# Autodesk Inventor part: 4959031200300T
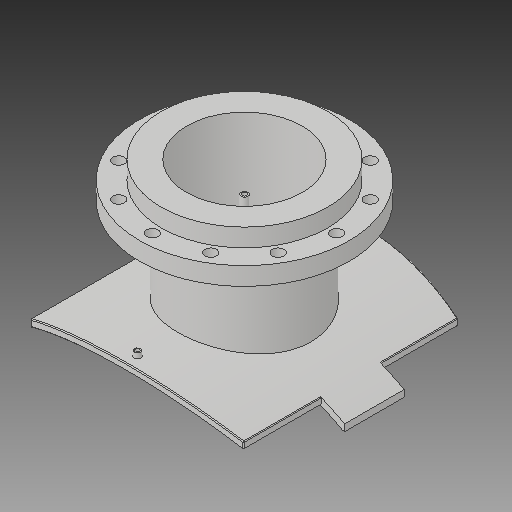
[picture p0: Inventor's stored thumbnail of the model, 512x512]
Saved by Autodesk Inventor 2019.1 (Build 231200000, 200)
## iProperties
Created: 2017-10
Part Number: 4959031200300T
Material: Generic
Description: PLASSON FLANGED BRANCH SADDLE 1200X300
Document SubType Name: Modeling
Designer: KIM
Mass: 2339.99 g
Surface Area: 3251.55 cm^2
Volume: 2339.99 cm^3
Density: 1 g/cm^3
Appearance: Default
Author: KIM
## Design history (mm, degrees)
derived "495904_495903.ipt"
feature "Solid1::495904_495903.ipt"
feature "Solid2::495904_495903.ipt"
tag "TaggingFeature1"
body "Solid1"
other parameters: "d1" = 15, "d2" = 473.4, "d4" = 0, "d6" = 132.5, "d7" = 0, "d12" = 625.6, "d13" = 14, "d14" = 238.5, "d16" = 5 deg, "d18" = 4, "d19" = 14, "d20" = 0, "d21" = 3, "d22" = 0, "d36" = 238.5, "d38" = 0, "d39" = 2, "d41" = 257, "d43" = 467, "d46" = 296, "d47" = 16, "d48" = 10.4, "d49" = 192.5, "d51" = 1224, "d53" = 0, "d54" = 26, "d55" = 205, "d57" = 0, "d59" = 360 deg, "d63" = 0, "d66" = 275, "d67" = 15, "d68" = 137.5, "d70" = 0, "d71" = 2, "d72" = 526, "B_" = 526, "H_" = 275, "x_" = 15, "D_" = 16, "DN_" = 257, "D_1" = 467, "s_" = 26
